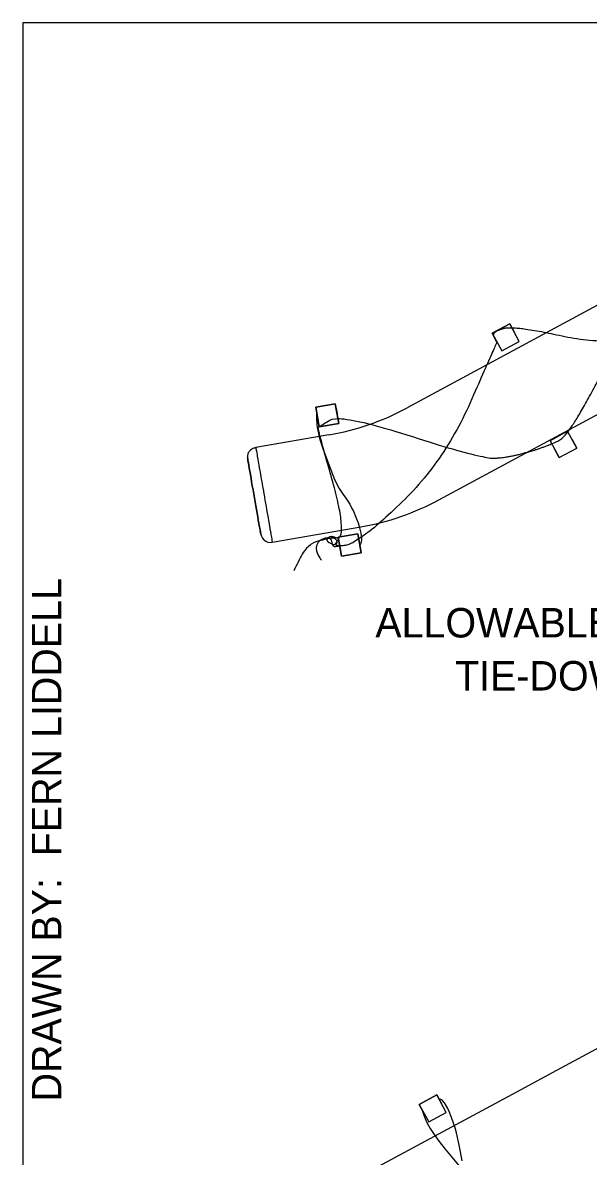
# Model space of a CAD drawing. Extents: x 99862 to 103680, y 99470 to 102076.
# Drawn here: x 99862 to 100169, y 101460 to 102076 of the extents above; entities that cross this region are included whole.
import ezdxf

# ---------------------------------------------------------------- set-up
doc = ezdxf.new("R2010")
doc.units = 0
for name, color, linetype in [('Level 1', 7, 'Continuous'), ('Level 17', 7, 'Continuous'), ('Level 20', 7, 'Continuous'), ('Level 4', 7, 'Continuous'), ('Level 6', 7, 'Continuous'), ('Level 62', 7, 'Continuous'), ('Level 8', 7, 'Continuous')]:
    doc.layers.add(name, color=color, linetype=linetype)

msp = doc.modelspace()

# ---------------------------------------------------------------- linework, layer by layer
at = {"layer": 'Level 1'}
msp.add_lwpolyline([(99862, 99999.5), (103151, 99999.5), (103151, 102075.5), (99862, 102075.5)], close=True, dxfattribs=at)
at = {"layer": 'Level 17'}
msp.add_open_spline([(99904.41, 101312.2), (99973.17, 101329.36), (100131.55, 101422.53), (100314.34, 101443.21), (100464.97, 101568.49), (100562.31, 101613.81)], degree=3, dxfattribs=at)
at = {"layer": 'Level 4'}
for points in [[(100021.63, 101863.54), (100021.61, 101863.49), (100021.54, 101862.69), (100021.54, 101862.11), (100021.55, 101860.53), (100021.73, 101857.54), (100021.96, 101855.68), (100022.55, 101852.43), (100022.99, 101850.6), (100023.54, 101848.64), (100024.95, 101844.29), (100026.74, 101839.33), (100031.34, 101827.4)], [(100031.34, 101827.4), (100033.91, 101822.57), (100035.27, 101820.4), (100036.06, 101819.25), (100037.47, 101817.27), (100039.53, 101814.03), (100040.78, 101811.73), (100041.56, 101810.17), (100042.96, 101807.02), (100044.13, 101803.91), (100044.76, 101801.92), (100045.64, 101798.24), (100045.94, 101795.86), (100045.96, 101794.84), (100045.73, 101793.16), (100045.47, 101792.53), (100045.03, 101792.05)], [(100100.64, 101457.58), (100099.68, 101462.42), (100098.78, 101466.98), (100097.51, 101472.66), (100096.79, 101475.36), (100094.86, 101481.02), (100093.48, 101484.3), (100092.58, 101486.2), (100090.97, 101489.07), (100090, 101490.3), (100089.58, 101490.65), (100088.75, 101490.9), (100088.16, 101490.79), (100088.16, 101490.78)], [(100078.86, 101485.27), (100078.85, 101485.21), (100079.04, 101484.43), (100079.22, 101483.88), (100079.73, 101482.39), (100080.85, 101479.61), (100081.65, 101477.91), (100083.25, 101475.02), (100084.24, 101473.42), (100085.38, 101471.74), (100088.09, 101468.06), (100091.36, 101463.92), (100099.5, 101454.06)]]:
    msp.add_lwpolyline(points, dxfattribs=at)
for points in [[(100305.68, 101993.3), (100302.04, 101998.93), (100315.85, 102022.2), (100311.49, 101993.48), (100308.17, 101985.96), (100283.69, 101943.29), (100252.9, 101904.3), (100259.6, 101896.53), (100259.6, 101896.53), (100266.68, 101909.44), (100266.68, 101914.85), (100182.36, 101899.07), (100128.8, 101911.11), (100116.25, 101907.36), (100119.47, 101902.1), (100119.47, 101902.1), (100091.11, 101837.67), (100044.89, 101792.81), (100029.2, 101790.49), (100037.91, 101799.65), (100021.96, 101855.68), (100022.93, 101856.06), (100034.32, 101863.31), (100109.93, 101839.05), (100125.08, 101839.05), (100148.65, 101846.07), (100158.53, 101851.78), (100181.34, 101894.25), (100198.08, 101914.33), (100237.52, 101963.34), (100234.32, 101969.75), (100223.21, 101964.1), (100225.76, 101959.36), (100294.94, 101952.05), (100355.91, 101959.93), (100364.6, 101967.65), (100363.89, 101968.77), (100351.87, 101968.77), (100328.45, 101926.33)], [(100033.49, 101795.34), (100030.15, 101796.51), (100028.86, 101796.31), (100027.21, 101795.53), (100027.15, 101793.97), (100029.11, 101792.8), (100030.95, 101791.94), (100033.22, 101793.21), (100031.76, 101795.6), (100028.7, 101795.6), (100014.99, 101792.12), (100009.27, 101777.83)], [(100034.14, 101791.44), (100031.82, 101790.86), (100030.4, 101791.1), (100029.41, 101796.29), (100022.55, 101794.68), (100020.62, 101788.45), (100024.18, 101783.67)]]:
    msp.add_open_spline(points, degree=2, dxfattribs=at)
at = {"layer": 'Level 6'}
for p, q in [((100116.91, 101906.84), (100126.42, 101911.96)), ((100126.42, 101911.96), (100116.91, 101906.83)), ((100126.42, 101911.96), (100126.42, 101911.96)), ((100126.42, 101911.96), (100126.42, 101911.96)), ((100126.42, 101911.96), (100128.97, 101907.22)), ((100131.56, 101902.41), (100126.42, 101911.96)), ((100126.45, 101911.9), (100126.45, 101911.91)), ((100116.91, 101906.84), (100116.91, 101906.83)), ((100116.91, 101906.84), (100116.91, 101906.84)), ((100119.46, 101902.1), (100116.91, 101906.84)), ((100116.91, 101906.83), (100122.05, 101897.29)), ((100116.94, 101906.78), (100116.94, 101906.78)), ((100122.05, 101897.29), (100131.56, 101902.41)), ((100131.56, 101902.41), (100131.56, 101902.41)), ((100122.05, 101897.29), (100122.05, 101897.29)), ((100021.08, 101866.71), (100031.72, 101868.56)), ((100021.08, 101866.7), (100031.73, 101868.55)), ((100031.73, 101868.55), (100021.08, 101866.7)), ((100031.73, 101868.55), (100031.72, 101868.56)), ((100031.72, 101868.56), (100031.72, 101868.56)), ((100031.72, 101868.56), (100032.65, 101863.25)), ((100031.73, 101868.55), (100033.58, 101857.91)), ((100033.58, 101857.91), (100031.73, 101868.55)), ((100031.73, 101868.53), (100031.73, 101868.53)), ((100021.08, 101866.71), (100021.08, 101866.7)), ((100021.08, 101866.71), (100021.08, 101866.71)), ((100022.01, 101861.4), (100021.08, 101866.71)), ((100022.93, 101856.06), (100021.08, 101866.7)), ((100021.08, 101866.7), (100022.93, 101856.06)), ((100021.09, 101866.68), (100021.09, 101866.68)), ((100033.58, 101857.91), (100022.93, 101856.06)), ((100022.93, 101856.06), (100033.58, 101857.91)), ((100022.93, 101856.06), (100022.93, 101856.06)), ((100033.58, 101857.91), (100033.58, 101857.91)), ((100160.24, 101849.19), (100162.79, 101844.45)), ((100153.28, 101839.33), (100150.73, 101844.07)), ((100033.37, 101796.07), (100044.01, 101797.92)), ((100044.01, 101797.92), (100033.37, 101796.07)), ((100033.37, 101796.07), (100035.14, 101785.86)), ((100035.14, 101785.85), (100034.22, 101791.16)), ((100045.78, 101787.71), (100035.14, 101785.86)), ((100035.14, 101785.86), (100045.78, 101787.71)), ((100044.86, 101793.01), (100045.78, 101787.7)), ((100045.78, 101787.71), (100045.78, 101787.71)), ((100077.3, 101488.17), (100086.81, 101493.29)), ((100086.81, 101493.28), (100077.3, 101488.16)), ((100086.81, 101493.28), (100086.81, 101493.29)), ((100086.81, 101493.29), (100089.36, 101488.55)), ((100086.81, 101493.28), (100086.81, 101493.28)), ((100091.95, 101483.74), (100086.81, 101493.28)), ((100086.84, 101493.23), (100086.84, 101493.23)), ((100077.3, 101488.17), (100077.3, 101488.16)), ((100079.85, 101483.42), (100077.3, 101488.17)), ((100077.3, 101488.16), (100077.3, 101488.16)), ((100077.3, 101488.16), (100082.44, 101478.62)), ((100077.33, 101488.11), (100077.33, 101488.11)), ((100082.44, 101478.62), (100091.95, 101483.74)), ((100091.95, 101483.74), (100091.95, 101483.74)), ((100082.44, 101478.62), (100082.44, 101478.62))]:
    msp.add_line(p, q, dxfattribs=at)
for points in [[(100128.97, 101907.22), (100128.97, 101907.22), (100126.42, 101911.96)], [(100116.91, 101906.84), (100119.46, 101902.1), (100119.46, 101902.1)], [(100032.65, 101863.25), (100032.65, 101863.25), (100031.72, 101868.56)], [(100021.08, 101866.71), (100022.01, 101861.4), (100022.01, 101861.4)], [(100148.35, 101848.49), (100153.28, 101839.33), (100153.28, 101839.33), (100162.79, 101844.45), (100162.79, 101844.46), (100157.86, 101853.61), (100148.35, 101848.49)], [(100162.79, 101844.45), (100162.79, 101844.45), (100160.24, 101849.19)], [(100150.73, 101844.07), (100153.28, 101839.33), (100153.28, 101839.33)], [(100033.37, 101796.07), (100035.14, 101785.86), (100035.14, 101785.85), (100045.78, 101787.7), (100045.78, 101787.71), (100044.01, 101797.92), (100033.37, 101796.07)], [(100035.14, 101785.86), (100035.14, 101785.86), (100033.37, 101796.07), (100033.37, 101796.07)], [(100033.37, 101796.07), (100033.37, 101796.07), (100035.14, 101785.86), (100035.14, 101785.86)], [(100044.01, 101797.92), (100044.01, 101797.92), (100045.78, 101787.71), (100045.78, 101787.71)], [(100045.78, 101787.71), (100045.78, 101787.71), (100044.01, 101797.92), (100044.01, 101797.92)], [(100034.22, 101791.16), (100035.14, 101785.86), (100035.14, 101785.86)], [(100045.78, 101787.71), (100045.78, 101787.71), (100044.86, 101793.01)], [(100089.36, 101488.55), (100089.36, 101488.55), (100086.81, 101493.28)], [(100077.3, 101488.16), (100079.85, 101483.42), (100079.85, 101483.42)]]:
    msp.add_lwpolyline(points, dxfattribs=at)
at = {"layer": 'Level 8'}
for p, q in [((99984.15, 101838.63), (99984.05, 101839.24)), ((99984.32, 101837.68), (99984.15, 101838.63)), ((99984.76, 101835.17), (99984.32, 101837.68)), ((99985.02, 101833.65), (99984.76, 101835.17)), ((99985.31, 101831.97), (99985.02, 101833.65)), ((99985.96, 101828.22), (99985.31, 101831.97)), ((99986.32, 101826.19), (99985.96, 101828.22)), ((99986.68, 101824.08), (99986.32, 101826.19)), ((99987.06, 101821.92), (99986.68, 101824.08)), ((99987.83, 101817.52), (99987.44, 101819.72)), ((99987.84, 101817.46), (99987.83, 101817.52)), ((99988.21, 101815.33), (99987.84, 101817.46)), ((99988.58, 101813.19), (99988.21, 101815.33)), ((99988.94, 101811.1), (99988.58, 101813.19)), ((99989.29, 101809.1), (99988.94, 101811.1)), ((99989.62, 101807.21), (99989.29, 101809.1)), ((99989.93, 101805.44), (99989.62, 101807.21)), ((99990.21, 101803.82), (99989.93, 101805.44))]:
    msp.add_line(p, q, dxfattribs=at)
for points in [[(100188.93, 101930.01), (100169.46, 101919.52), (100070.7, 101866.33)], [(100088.01, 101816.41), (100194.19, 101873.61), (100212.43, 101883.43)], [(100028.29, 101851.65), (99988.57, 101844.74), (99987.79, 101844.55), (99987.41, 101844.41), (99987.04, 101844.27), (99986.89, 101844.2), (99986.35, 101843.88), (99986.2, 101843.8), (99985.59, 101843.33), (99985.48, 101843.22), (99985.43, 101843.17), (99984.96, 101842.66), (99984.72, 101842.3), (99984.55, 101842.04), (99984.48, 101841.92), (99984.23, 101841.33), (99984.2, 101841.25), (99984.03, 101840.56), (99984.01, 101840.4), (99984.01, 101840.29), (99984, 101839.7), (99984.05, 101839.24), (99984.15, 101838.63), (99984.32, 101837.68), (99984.52, 101836.52), (99984.76, 101835.17), (99985.02, 101833.65), (99985.31, 101831.97), (99985.63, 101830.16), (99985.96, 101828.22), (99986.32, 101826.19), (99986.68, 101824.08), (99987.06, 101821.92), (99987.44, 101819.72), (99987.83, 101817.52), (99988.21, 101815.33), (99988.58, 101813.19), (99988.94, 101811.1), (99989.29, 101809.1), (99989.62, 101807.21), (99989.93, 101805.44), (99990.21, 101803.82), (99990.46, 101802.36), (99990.68, 101801.08), (99990.87, 101799.99), (99991.03, 101799.11), (99991.14, 101798.44), (99991.22, 101797.99), (99991.26, 101797.77)], [(99988.57, 101844.74), (99988.62, 101844.46), (99988.83, 101843.26), (99988.86, 101843.09), (99989.08, 101841.82), (99989.23, 101840.96), (99989.37, 101840.13), (99989.67, 101838.43), (99989.7, 101838.23), (99990.07, 101836.14), (99990.18, 101835.49), (99990.46, 101833.87), (99990.75, 101832.24), (99990.88, 101831.45), (99991.33, 101828.91), (99991.36, 101828.74), (99991.78, 101826.27), (99992, 101825.04), (99992.25, 101823.57), (99992.66, 101821.25), (99992.73, 101820.82), (99993.21, 101818.07), (99993.32, 101817.43), (99993.69, 101815.34), (99993.98, 101813.67), (99994.15, 101812.65), (99994.61, 101810.05), (99995.04, 101807.55), (99995.21, 101806.6), (99995.45, 101805.18), (99995.76, 101803.43), (99995.84, 101802.97), (99996.19, 101800.94), (99996.25, 101800.62), (99996.51, 101799.12), (99996.66, 101798.21), (99996.78, 101797.52), (99997.01, 101796.22), (99997.02, 101796.16), (99997.21, 101795.06), (99997.26, 101794.77), (99997.36, 101794.22), (99997.43, 101793.81), (99997.46, 101793.66), (99997.5, 101793.38)], [(99987.44, 101819.72), (99987.27, 101820.69), (99987.06, 101821.92)], [(99990.46, 101802.36), (99990.45, 101802.4), (99990.25, 101803.55), (99990.21, 101803.82)], [(99990.68, 101801.08), (99990.68, 101801.12), (99990.46, 101802.36)], [(99991.03, 101799.11), (99991.02, 101799.14), (99990.87, 101800.03), (99990.68, 101801.08)], [(99996.3, 101793.31), (99997.5, 101793.38), (100045.57, 101801.73)], [(99991.14, 101798.44), (99991.14, 101798.46), (99991.03, 101799.11)], [(99991.22, 101797.99), (99991.22, 101798), (99991.14, 101798.44)], [(99991.26, 101797.77), (99991.26, 101797.77), (99991.22, 101797.99)], [(99991.26, 101797.77), (99991.6, 101796.61), (99992.19, 101795.55), (99993, 101794.66), (99993.99, 101793.96), (99995.1, 101793.5), (99996.3, 101793.31)], [(100261.12, 101565.37), (100201.17, 101533.07), (100151.9, 101506.53)], [(100151.9, 101506.53), (100132.43, 101496.04), (100033.68, 101442.85)]]:
    msp.add_lwpolyline(points, dxfattribs=at)
for centre, start, end in [((100004.31, 101989.58), 279.8639, 298.31029), ((100021.61, 101939.66), 279.85568, 298.31028)]:
    msp.add_arc(centre, 140, start, end, dxfattribs=at)

# ---------------------------------------------------------------- texts
at = {"layer": 'Level 20'}
for s, p in [('ALLOWABLE ALTERNATIVE ', (100053.45, 101741.68)), ('TIE-DOWN METHOD', (100096.77, 101712.88))]:
    msp.add_text(s, height=16, dxfattribs=at).set_placement(p)
at = {"layer": 'Level 62'}
msp.add_text('DRAWN BY:  FERN LIDDELL', height=16, rotation=90, dxfattribs=at).set_placement((99883, 101489.76))

doc.saveas('drawing.dxf')
